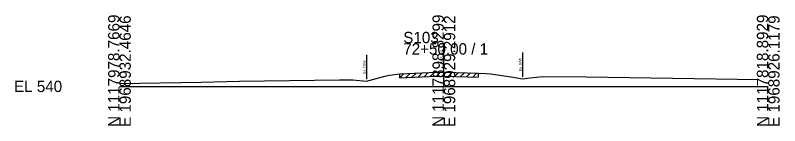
# Model space of a CAD drawing. Extents: x -26 to 163, y -10 to 24018.
# Drawn here: x -25.7 to 162.8, y 20490.3 to 20517.5 of the extents above; entities that cross this region are included whole.
import ezdxf

# ---------------------------------------------------------------- set-up
doc = ezdxf.new("R2010")
doc.units = 0
for name, color, linetype in [('RD_GPK_XS_Cell', 7, 'Continuous'), ('RD_XS_ExGround', 7, 'Continuous'), ('RD_XS_ExPaveRet', 7, 'Continuous'), ('RD_XS_ExRW', 7, 'Continuous'), ('RD_XS_TX_Elev_EX', 7, 'Continuous')]:
    doc.layers.add(name, color=color, linetype=linetype)

msp = doc.modelspace()

# ---------------------------------------------------------------- linework, layer by layer
at = {"layer": 'RD_GPK_XS_Cell'}
for p, q in [((80, 20500), (80, 20510.63)), ((0, 20500), (80, 20500)), ((80, 20500), (160, 20500))]:
    msp.add_line(p, q, dxfattribs=at)
at = {"layer": 'RD_XS_ExGround'}
msp.add_lwpolyline([(0, 20500.73), (20.11, 20501.05), (29.58, 20501.27), (54.25, 20501.61), (57.15, 20501.64), (57.57, 20501.61), (60.95, 20501.26), (63.66, 20502.04), (65.42, 20502.54), (66.62, 20502.72), (69.13, 20503.11), (76.38, 20503.4), (80.08, 20503.54), (82.92, 20503.44), (88.47, 20503.24), (90.43, 20503.15), (91.49, 20503.1), (96.62, 20502.31), (99.43, 20501.87), (101.26, 20502.09), (104.41, 20502.45), (115.13, 20502.31), (157.72, 20501.67)], dxfattribs=at)
at = {"layer": 'RD_XS_ExPaveRet'}
for p, q in [((69.13, 20502.11), (70.17, 20503.15)), ((69.13, 20502.11), (69.13, 20503.11)), ((70.63, 20502.17), (71.67, 20503.21)), ((72.13, 20502.23), (73.17, 20503.27)), ((73.63, 20502.29), (74.67, 20503.33)), ((75.13, 20502.35), (76.17, 20503.39)), ((76.63, 20502.41), (77.67, 20503.45)), ((78.13, 20502.47), (79.17, 20503.51)), ((79.63, 20502.53), (80.62, 20503.52)), ((81.13, 20502.51), (82.09, 20503.47)), ((82.63, 20502.45), (83.59, 20503.42)), ((84.13, 20502.4), (85.09, 20503.36)), ((85.63, 20502.34), (86.59, 20503.31)), ((87.13, 20502.29), (88.09, 20503.26)), ((88.47, 20503.24), (88.47, 20502.24)), ((69.13, 20502.11), (76.38, 20502.4)), ((76.38, 20502.4), (80.08, 20502.54)), ((80.08, 20502.54), (82.92, 20502.44)), ((82.92, 20502.44), (88.47, 20502.24))]:
    msp.add_line(p, q, dxfattribs=at)
at = {"layer": 'RD_XS_ExRW'}
for p, q in [((60.95, 20507.76), (60.95, 20501.76)), ((99.43, 20508.37), (99.43, 20502.37))]:
    msp.add_line(p, q, dxfattribs=at)

# ---------------------------------------------------------------- texts
at = {"layer": 'RD_GPK_XS_Cell'}
for s, p in [('N 1117978.7669', (0, 20490)), ('E 1968932.4646', (2.8, 20490)), ('N 1117898.8299', (80, 20490)), ('E 1968929.2912', (82.8, 20490)), ('N 1117818.8929', (160, 20490)), ('E 1968926.1179', (162.8, 20490))]:
    msp.add_text(s, height=2.8, rotation=90, dxfattribs=at).set_placement(p)
for s, p in [('S103', (70, 20510.63)), ('72+50.00 / 1', (70, 20507.83)), ('EL 540', (-26, 20498.6))]:
    msp.add_text(s, height=2.8, dxfattribs=at).set_placement(p)
at = {"layer": 'RD_XS_ExRW'}
for p in [(99.18, 20503.71), (60.7, 20503.1)]:
    msp.add_text('Ex. R/W ', height=0.65, rotation=90, dxfattribs=at).set_placement(p)
at = {"layer": 'RD_XS_TX_Elev_EX'}
msp.add_text('543.54', height=0.8, rotation=90, dxfattribs=at).set_placement((79.9, 20505.54))

doc.saveas('drawing.dxf')
